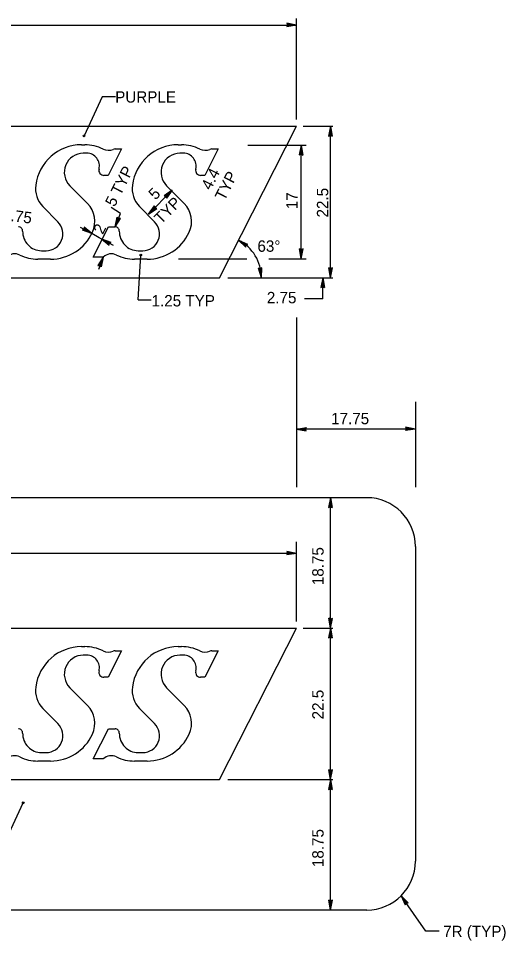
# Model space of a CAD drawing. Extents: x 10268197 to 10269179, y 2141503 to 2142677.
# Drawn here: x 10268632.3 to 10268662.3, y 2142210.9 to 2142267.6 of the extents above; entities that cross this region are included whole.
import ezdxf

# ---------------------------------------------------------------- set-up
doc = ezdxf.new("R2010")
doc.units = 0
for name, color, linetype in [('1', 7, 'Continuous'), ('2', 7, 'Continuous'), ('21', 7, 'Continuous')]:
    doc.layers.add(name, color=color, linetype=linetype)

msp = doc.modelspace()

# ---------------------------------------------------------------- linework, layer by layer
at = {"layer": '1'}
for p, q in [((10268627.004, 2142267.213), (10268649.465, 2142267.213)), ((10268648.907, 2142267.223), (10268648.859, 2142267.117)), ((10268649.465, 2142267.213), (10268648.859, 2142267.117)), ((10268649.465, 2142267.213), (10268648.863, 2142267.33)), ((10268648.863, 2142267.33), (10268648.907, 2142267.223)), ((10268649.465, 2142267.213), (10268648.885, 2142267.173)), ((10268649.465, 2142267.213), (10268648.887, 2142267.274)), ((10268649.465, 2142261.41), (10268649.465, 2142267.627)), ((10268637.499, 2142262.81), (10268636.384, 2142260.402)), ((10268638.321, 2142262.81), (10268637.499, 2142262.81)), ((10268649.878, 2142260.995), (10268651.71, 2142260.995)), ((10268651.553, 2142260.995), (10268651.436, 2142260.394)), ((10268651.553, 2142260.995), (10268651.493, 2142260.417)), ((10268651.553, 2142251.679), (10268651.553, 2142260.995)), ((10268651.553, 2142260.995), (10268651.649, 2142260.39)), ((10268651.553, 2142260.995), (10268651.594, 2142260.416)), ((10268651.436, 2142260.394), (10268651.543, 2142260.438)), ((10268651.543, 2142260.438), (10268651.649, 2142260.39)), ((10268646.461, 2142259.831), (10268650.063, 2142259.831)), ((10268649.75, 2142259.831), (10268649.633, 2142259.229)), ((10268649.75, 2142259.831), (10268649.689, 2142259.253)), ((10268649.75, 2142252.844), (10268649.75, 2142259.831)), ((10268649.75, 2142259.831), (10268649.845, 2142259.226)), ((10268649.75, 2142259.831), (10268649.79, 2142259.251)), ((10268649.633, 2142259.229), (10268649.74, 2142259.274)), ((10268649.74, 2142259.274), (10268649.845, 2142259.226)), ((10268640.355, 2142255.594), (10268641.818, 2142257.058)), ((10268641.818, 2142257.058), (10268641.31, 2142256.715)), ((10268641.818, 2142257.058), (10268641.366, 2142256.692)), ((10268641.818, 2142257.058), (10268641.437, 2142256.619)), ((10268641.818, 2142257.058), (10268641.458, 2142256.562)), ((10268641.31, 2142256.715), (10268641.418, 2142256.67)), ((10268641.418, 2142256.67), (10268641.458, 2142256.562)), ((10268638.62, 2142255.631), (10268638.045, 2142255.997)), ((10268640.355, 2142255.594), (10268640.714, 2142256.09)), ((10268640.355, 2142255.594), (10268640.736, 2142256.032)), ((10268640.355, 2142255.594), (10268640.806, 2142255.96)), ((10268640.355, 2142255.594), (10268640.863, 2142255.937)), ((10268640.755, 2142255.981), (10268640.714, 2142256.09)), ((10268640.863, 2142255.937), (10268640.755, 2142255.981)), ((10268638.297, 2142254.807), (10268638.62, 2142255.631)), ((10268638.297, 2142254.807), (10268638.429, 2142255.406)), ((10268638.297, 2142254.807), (10268638.471, 2142255.361)), ((10268638.297, 2142254.807), (10268638.625, 2142255.324)), ((10268638.297, 2142254.807), (10268638.564, 2142255.324)), ((10268638.509, 2142255.323), (10268638.429, 2142255.406)), ((10268638.625, 2142255.324), (10268638.509, 2142255.323)), ((10268636.864, 2142254.388), (10268636.165, 2142254.769)), ((10268637.319, 2142254.14), (10268636.864, 2142254.388)), ((10268638.205, 2142253.657), (10268637.319, 2142254.14)), ((10268645.892, 2142253.985), (10268646.453, 2142253.736)), ((10268645.892, 2142253.985), (10268646.334, 2142253.56)), ((10268645.892, 2142253.985), (10268646.345, 2142253.619)), ((10268645.892, 2142253.985), (10268646.4, 2142253.704)), ((10268646.334, 2142253.56), (10268646.355, 2142253.674)), ((10268646.355, 2142253.674), (10268646.453, 2142253.736)), ((10268639.718, 2142250.319), (10268639.876, 2142253.071)), ((10268649.75, 2142252.844), (10268649.654, 2142253.449)), ((10268649.759, 2142253.401), (10268649.654, 2142253.449)), ((10268649.75, 2142252.844), (10268649.709, 2142253.423)), ((10268649.75, 2142252.844), (10268649.866, 2142253.446)), ((10268649.75, 2142252.844), (10268649.81, 2142253.422)), ((10268649.866, 2142253.446), (10268649.759, 2142253.401)), ((10268637.571, 2142252.949), (10268637.242, 2142252.431)), ((10268637.242, 2142252.431), (10268637.358, 2142252.433)), ((10268637.571, 2142252.949), (10268637.268, 2142252.177)), ((10268637.571, 2142252.949), (10268637.303, 2142252.432)), ((10268637.358, 2142252.433), (10268637.439, 2142252.35)), ((10268637.571, 2142252.949), (10268637.396, 2142252.394)), ((10268637.571, 2142252.949), (10268637.439, 2142252.35)), ((10268642.205, 2142252.844), (10268646.4, 2142252.844)), ((10268647.753, 2142252.844), (10268650.063, 2142252.844)), ((10268647.306, 2142251.679), (10268647.126, 2142252.266)), ((10268647.238, 2142252.233), (10268647.126, 2142252.266)), ((10268647.306, 2142251.679), (10268647.185, 2142252.248)), ((10268647.338, 2142252.292), (10268647.238, 2142252.233)), ((10268647.306, 2142251.679), (10268647.285, 2142252.261)), ((10268647.306, 2142251.679), (10268647.338, 2142252.292)), ((10268651.553, 2142251.679), (10268651.457, 2142252.285)), ((10268651.562, 2142252.237), (10268651.457, 2142252.285)), ((10268651.553, 2142251.679), (10268651.513, 2142252.259)), ((10268651.553, 2142251.679), (10268651.67, 2142252.281)), ((10268651.553, 2142251.679), (10268651.614, 2142252.258)), ((10268651.67, 2142252.281), (10268651.562, 2142252.237)), ((10268645.235, 2142251.679), (10268651.71, 2142251.679)), ((10268651.081, 2142251.679), (10268650.965, 2142251.078)), ((10268651.081, 2142251.679), (10268651.021, 2142251.101)), ((10268651.081, 2142250.386), (10268651.081, 2142251.679)), ((10268651.081, 2142251.679), (10268651.177, 2142251.074)), ((10268651.081, 2142251.679), (10268651.122, 2142251.1)), ((10268650.965, 2142251.078), (10268651.072, 2142251.122)), ((10268651.072, 2142251.122), (10268651.177, 2142251.074)), ((10268639.718, 2142250.319), (10268640.521, 2142250.319)), ((10268651.081, 2142250.386), (10268649.956, 2142250.386)), ((10268649.465, 2142249.232), (10268649.465, 2142238.799)), ((10268656.784, 2142244.041), (10268656.784, 2142238.799)), ((10268656.227, 2142242.379), (10268656.179, 2142242.273)), ((10268656.784, 2142242.369), (10268656.179, 2142242.273)), ((10268656.784, 2142242.369), (10268656.182, 2142242.486)), ((10268656.182, 2142242.486), (10268656.227, 2142242.379)), ((10268656.784, 2142242.369), (10268656.205, 2142242.329)), ((10268656.784, 2142242.369), (10268656.206, 2142242.43)), ((10268651.553, 2142238.146), (10268651.436, 2142237.545)), ((10268651.553, 2142238.146), (10268651.493, 2142237.568)), ((10268651.553, 2142230.12), (10268651.553, 2142238.146)), ((10268651.553, 2142238.146), (10268651.649, 2142237.541)), ((10268651.553, 2142238.146), (10268651.594, 2142237.567)), ((10268651.436, 2142237.545), (10268651.543, 2142237.589)), ((10268651.543, 2142237.589), (10268651.649, 2142237.541)), ((10268649.465, 2142230.534), (10268649.465, 2142235.426)), ((10268648.907, 2142234.732), (10268648.859, 2142234.626)), ((10268649.465, 2142234.722), (10268648.859, 2142234.626)), ((10268649.465, 2142234.722), (10268648.863, 2142234.839)), ((10268648.863, 2142234.839), (10268648.907, 2142234.732)), ((10268649.465, 2142234.722), (10268648.885, 2142234.682)), ((10268649.465, 2142234.722), (10268648.887, 2142234.783)), ((10268651.553, 2142230.12), (10268651.457, 2142230.726)), ((10268651.562, 2142230.678), (10268651.457, 2142230.726)), ((10268651.553, 2142230.12), (10268651.513, 2142230.7)), ((10268651.553, 2142230.12), (10268651.67, 2142230.722)), ((10268651.553, 2142230.12), (10268651.614, 2142230.699)), ((10268651.67, 2142230.722), (10268651.562, 2142230.678)), ((10268649.878, 2142230.12), (10268651.71, 2142230.12)), ((10268651.553, 2142230.12), (10268651.436, 2142229.518)), ((10268651.553, 2142230.12), (10268651.493, 2142229.541)), ((10268651.553, 2142220.804), (10268651.553, 2142230.12)), ((10268651.553, 2142230.12), (10268651.649, 2142229.514)), ((10268651.553, 2142230.12), (10268651.594, 2142229.541)), ((10268651.436, 2142229.518), (10268651.543, 2142229.563)), ((10268651.543, 2142229.563), (10268651.649, 2142229.514)), ((10268651.553, 2142220.804), (10268651.457, 2142221.409)), ((10268651.562, 2142221.361), (10268651.457, 2142221.409)), ((10268651.553, 2142220.804), (10268651.513, 2142221.384)), ((10268651.553, 2142220.804), (10268651.67, 2142221.406)), ((10268651.553, 2142220.804), (10268651.614, 2142221.383)), ((10268651.67, 2142221.406), (10268651.562, 2142221.361)), ((10268645.235, 2142220.804), (10268651.71, 2142220.804)), ((10268651.553, 2142220.804), (10268651.436, 2142220.202)), ((10268651.553, 2142220.804), (10268651.493, 2142220.225)), ((10268651.553, 2142212.778), (10268651.553, 2142220.804)), ((10268651.553, 2142220.804), (10268651.649, 2142220.198)), ((10268651.553, 2142220.804), (10268651.594, 2142220.224)), ((10268651.436, 2142220.202), (10268651.543, 2142220.247)), ((10268651.543, 2142220.247), (10268651.649, 2142220.198)), ((10268631.525, 2142216.966), (10268632.64, 2142219.374)), ((10268651.553, 2142212.778), (10268651.457, 2142213.383)), ((10268651.562, 2142213.335), (10268651.457, 2142213.383)), ((10268651.553, 2142212.778), (10268651.513, 2142213.358)), ((10268651.553, 2142212.778), (10268651.67, 2142213.38)), ((10268651.553, 2142212.778), (10268651.614, 2142213.357)), ((10268651.67, 2142213.38), (10268651.562, 2142213.335)), ((10268657.416, 2142211.474), (10268655.906, 2142213.656)), ((10268658.238, 2142211.474), (10268657.416, 2142211.474))]:
    msp.add_line(p, q, dxfattribs=at)
for centre in [(10268636.384, 2142260.402), (10268639.876, 2142253.072), (10268632.64, 2142219.374)]:
    msp.add_circle(centre, 0.0518, dxfattribs=at)
msp.add_arc((10268644.718, 2142251.68), 2.588, 0, 63.0012, dxfattribs=at)
at = {"layer": '2'}
for p, q in [((10268619.941, 2142260.995), (10268649.465, 2142260.995)), ((10268644.718, 2142251.679), (10268649.465, 2142260.995)), ((10268636.229, 2142259.857), (10268636.425, 2142259.857)), ((10268642.18, 2142259.857), (10268642.377, 2142259.857)), ((10268636.556, 2142259.335), (10268636.334, 2142259.335)), ((10268638.691, 2142259.596), (10268637.868, 2142257.97)), ((10268638.302, 2142259.596), (10268638.691, 2142259.596)), ((10268642.508, 2142259.335), (10268642.286, 2142259.335)), ((10268644.642, 2142259.596), (10268643.82, 2142257.97)), ((10268644.254, 2142259.596), (10268644.642, 2142259.596)), ((10268637.868, 2142257.97), (10268637.61, 2142257.97)), ((10268643.82, 2142257.97), (10268643.561, 2142257.97)), ((10268635.511, 2142257.333), (10268636.596, 2142256.24)), ((10268641.463, 2142257.333), (10268642.548, 2142256.24)), ((10268634.78, 2142255.12), (10268633.848, 2142256.057)), ((10268640.731, 2142255.12), (10268639.8, 2142256.057)), ((10268636.942, 2142252.949), (10268637.882, 2142254.807)), ((10268637.882, 2142254.807), (10268638.297, 2142254.807)), ((10268633.768, 2142253.34), (10268634.048, 2142253.34)), ((10268639.72, 2142253.34), (10268639.999, 2142253.34)), ((10268634.326, 2142252.818), (10268633.547, 2142252.818)), ((10268637.571, 2142252.949), (10268636.942, 2142252.949)), ((10268640.278, 2142252.818), (10268639.499, 2142252.818)), ((10268619.077, 2142251.679), (10268644.718, 2142251.679)), ((10268656.784, 2142242.369), (10268649.465, 2142242.369)), ((10268653.784, 2142238.146), (10268592.784, 2142238.146)), ((10268656.784, 2142235.146), (10268656.784, 2142215.778)), ((10268649.465, 2142234.722), (10268597.104, 2142234.722)), ((10268619.941, 2142230.12), (10268649.465, 2142230.12)), ((10268644.718, 2142220.804), (10268649.465, 2142230.12)), ((10268636.229, 2142228.982), (10268636.425, 2142228.982)), ((10268638.691, 2142228.721), (10268637.868, 2142227.095)), ((10268638.302, 2142228.721), (10268638.691, 2142228.721)), ((10268642.18, 2142228.982), (10268642.377, 2142228.982)), ((10268644.642, 2142228.721), (10268643.82, 2142227.095)), ((10268644.254, 2142228.721), (10268644.642, 2142228.721)), ((10268636.556, 2142228.46), (10268636.334, 2142228.46)), ((10268642.508, 2142228.46), (10268642.286, 2142228.46)), ((10268637.868, 2142227.095), (10268637.61, 2142227.095)), ((10268643.82, 2142227.095), (10268643.561, 2142227.095)), ((10268635.511, 2142226.457), (10268636.596, 2142225.365)), ((10268641.463, 2142226.457), (10268642.548, 2142225.365)), ((10268634.78, 2142224.244), (10268633.848, 2142225.182)), ((10268640.731, 2142224.244), (10268639.8, 2142225.182)), ((10268636.942, 2142222.073), (10268637.882, 2142223.932)), ((10268637.882, 2142223.932), (10268638.297, 2142223.932)), ((10268633.768, 2142222.464), (10268634.048, 2142222.464)), ((10268639.72, 2142222.464), (10268639.999, 2142222.464)), ((10268634.326, 2142221.943), (10268633.547, 2142221.943)), ((10268637.571, 2142222.073), (10268636.942, 2142222.073)), ((10268640.278, 2142221.943), (10268639.499, 2142221.943)), ((10268619.077, 2142220.804), (10268644.718, 2142220.804)), ((10268653.784, 2142212.778), (10268592.784, 2142212.778))]:
    msp.add_line(p, q, dxfattribs=at)
for centre, start, end in [((10268653.784, 2142235.146), 0, 90), ((10268653.784, 2142215.778), 270, 0)]:
    msp.add_arc(centre, 3, start, end, dxfattribs=at)
for centre, major_axis, start_param, end_param in [((10268636.228, 2142256.989), (0, 2.868), 0, 1.436562), ((10268636.425, 2142257.25), (0, 2.607), 5.830963, 6.283185), ((10268642.18, 2142256.989), (0, 2.868), 0, 1.436562), ((10268642.376, 2142257.25), (0, 2.607), 5.830963, 6.283185), ((10268636.334, 2142258.163), (0, -1.173), 3.141593, 5.497787), ((10268636.556, 2142258.554), (0, -0.782), 1.321066, 3.141593), ((10268637.895, 2142260.299), (0, 0.782), 2.68937, 3.526171), ((10268638.302, 2142259.284), (0, 0.313), 0, 0.384579), ((10268642.286, 2142258.163), (0, -1.173), 3.141593, 5.497787), ((10268642.508, 2142258.554), (0, -0.782), 1.321066, 3.141593), ((10268643.846, 2142260.299), (0, 0.782), 2.68937, 3.526171), ((10268644.254, 2142259.284), (0, 0.313), 0, 0.384579), ((10268637.609, 2142258.283), (0, -0.313), 4.462658, 6.283185), ((10268643.561, 2142258.283), (0, -0.313), 4.462658, 6.283185), ((10268634.946, 2142257.164), (0, 1.564), 1.436562, 2.356194), ((10268640.898, 2142257.164), (0, 1.564), 1.436562, 2.356194), ((10268635.498, 2142255.134), (0, -1.564), 1.133591, 2.356194), ((10268641.45, 2142255.134), (0, -1.564), 1.133591, 2.356194), ((10268632.346, 2142254.546), (0, 0.261), 4.689114, 6.283185), ((10268634.047, 2142254.382), (0, -1.043), 0, 2.356194), ((10268638.297, 2142254.546), (0, 0.261), 4.689114, 6.283185), ((10268639.999, 2142254.382), (0, -1.043), 0, 2.356194), ((10268633.768, 2142254.513), (0, 1.173), 1.547521, 3.141593), ((10268634.326, 2142255.686), (0, -2.868), 0, 1.133591), ((10268639.72, 2142254.513), (0, 1.173), 1.547521, 3.141593), ((10268640.277, 2142255.686), (0, -2.868), 0, 1.133591), ((10268632.115, 2142252.416), (0, -0.73), 2.69443, 3.895387), ((10268633.547, 2142255.425), (0, -2.607), 5.836023, 6.283185), ((10268638.067, 2142252.416), (0, -0.73), 2.69443, 3.895387), ((10268639.499, 2142255.425), (0, -2.607), 5.836023, 6.283185), ((10268636.228, 2142226.114), (0, 2.868), 0, 1.436562), ((10268636.425, 2142226.375), (0, 2.607), 5.830963, 6.283185), ((10268637.895, 2142229.423), (0, 0.782), 2.68937, 3.526171), ((10268638.302, 2142228.408), (0, 0.313), 0, 0.384579), ((10268642.18, 2142226.114), (0, 2.868), 0, 1.436562), ((10268642.376, 2142226.375), (0, 2.607), 5.830963, 6.283185), ((10268643.846, 2142229.423), (0, 0.782), 2.68937, 3.526171), ((10268644.254, 2142228.408), (0, 0.313), 0, 0.384579), ((10268636.334, 2142227.287), (0, -1.173), 3.141593, 5.497787), ((10268636.556, 2142227.678), (0, -0.782), 1.321066, 3.141593), ((10268642.286, 2142227.287), (0, -1.173), 3.141593, 5.497787), ((10268642.508, 2142227.678), (0, -0.782), 1.321066, 3.141593), ((10268637.609, 2142227.408), (0, -0.313), 4.462658, 6.283185), ((10268643.561, 2142227.408), (0, -0.313), 4.462658, 6.283185), ((10268634.946, 2142226.289), (0, 1.564), 1.436562, 2.356194), ((10268640.898, 2142226.289), (0, 1.564), 1.436562, 2.356194), ((10268635.498, 2142224.259), (0, -1.564), 1.133591, 2.356194), ((10268641.45, 2142224.259), (0, -1.564), 1.133591, 2.356194), ((10268634.047, 2142223.507), (0, -1.043), 0, 2.356194), ((10268639.999, 2142223.507), (0, -1.043), 0, 2.356194), ((10268632.346, 2142223.671), (0, 0.261), 4.689114, 6.283185), ((10268633.768, 2142223.638), (0, 1.173), 1.547521, 3.141593), ((10268634.326, 2142224.811), (0, -2.868), 0, 1.133591), ((10268638.297, 2142223.671), (0, 0.261), 4.689114, 6.283185), ((10268639.72, 2142223.638), (0, 1.173), 1.547521, 3.141593), ((10268640.277, 2142224.811), (0, -2.868), 0, 1.133591), ((10268632.115, 2142221.541), (0, -0.73), 2.69443, 3.895387), ((10268633.547, 2142224.55), (0, -2.607), 5.836023, 6.283185), ((10268638.067, 2142221.541), (0, -0.73), 2.69443, 3.895387), ((10268639.499, 2142224.55), (0, -2.607), 5.836023, 6.283185)]:
    msp.add_ellipse(centre, major_axis=major_axis, ratio=0.992614, start_param=start_param, end_param=end_param, dxfattribs=at)
at = {"layer": '21'}
for p, q in [((10268636.391, 2142254.779), (10268636.379, 2142254.663)), ((10268636.864, 2142254.388), (10268636.384, 2142254.719)), ((10268636.864, 2142254.388), (10268636.391, 2142254.779)), ((10268636.379, 2142254.663), (10268636.286, 2142254.593)), ((10268636.864, 2142254.388), (10268636.286, 2142254.593)), ((10268636.864, 2142254.388), (10268636.335, 2142254.63)), ((10268637.451, 2142254.065), (10268638.029, 2142253.859)), ((10268637.451, 2142254.065), (10268637.924, 2142253.674)), ((10268637.451, 2142254.065), (10268637.93, 2142253.734)), ((10268637.451, 2142254.065), (10268637.98, 2142253.822)), ((10268637.924, 2142253.674), (10268637.936, 2142253.789)), ((10268637.936, 2142253.789), (10268638.029, 2142253.859)), ((10268649.465, 2142242.369), (10268650.07, 2142242.465)), ((10268649.465, 2142242.369), (10268650.045, 2142242.41)), ((10268649.465, 2142242.369), (10268650.066, 2142242.252)), ((10268649.465, 2142242.369), (10268650.043, 2142242.309)), ((10268650.022, 2142242.36), (10268650.07, 2142242.465)), ((10268650.066, 2142242.252), (10268650.022, 2142242.36)), ((10268655.906, 2142213.656), (10268656.337, 2142213.221)), ((10268655.906, 2142213.656), (10268656.162, 2142213.099)), ((10268655.906, 2142213.656), (10268656.194, 2142213.151)), ((10268655.906, 2142213.656), (10268656.277, 2142213.209)), ((10268656.162, 2142213.099), (10268656.223, 2142213.198)), ((10268656.223, 2142213.198), (10268656.337, 2142213.221))]:
    msp.add_line(p, q, dxfattribs=at)

# ---------------------------------------------------------------- texts
at = {"layer": '1'}
for s, p in [('PURPLE', (10268638.301, 2142262.447)), ('63°', (10268647.058, 2142253.272)), ('2.75', (10268647.637, 2142250.104)), ('1.25 TYP', (10268640.541, 2142249.912)), ('17.75', (10268651.594, 2142242.664)), ('7R (TYP)', (10268658.491, 2142211.112))]:
    msp.add_text(s, height=0.7, dxfattribs=at).set_placement(p)
for s, rotation, p in [('5 TYP', 62.9994, (10268638.27, 2142255.994)), ('4.4', 63, (10268644.184, 2142257.018)), ('TYP', 63, (10268645.03, 2142256.366)), ('5', 45, (10268640.776, 2142256.421)), ('22.5', 90, (10268651.417, 2142255.382)), ('TYP', 45, (10268641.129, 2142254.932)), ('17', 90, (10268649.537, 2142255.888)), ('3.75', 352.5994, (10268631.323, 2142255.236)), ('2', 63, (10268637.538, 2142254.295)), ('18.75', 90, (10268651.132, 2142232.762)), ('22.5', 90, (10268651.132, 2142224.507)), ('18.75', 90, (10268651.132, 2142215.419))]:
    msp.add_text(s, height=0.7, rotation=rotation, dxfattribs=at).set_placement(p)

doc.saveas('drawing.dxf')
